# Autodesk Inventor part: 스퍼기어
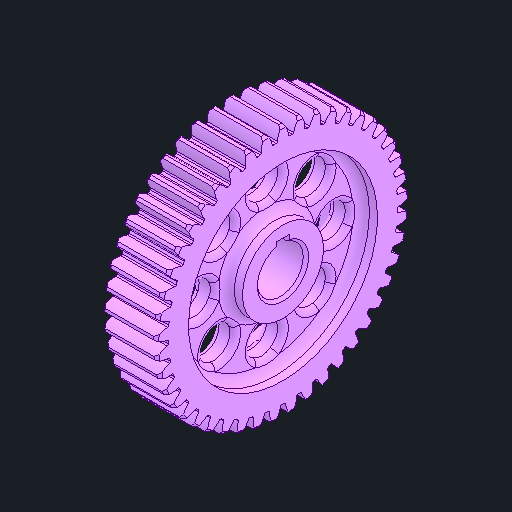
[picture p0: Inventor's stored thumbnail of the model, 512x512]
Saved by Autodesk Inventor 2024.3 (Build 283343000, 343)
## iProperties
Created: 2025-03
Part Number: 스퍼기어
Material: 강철, 합금
Document SubType Name: Modeling
Designer: user
Density: 7.73 g/cm^3
Appearance: 기본값
Author: jhkim
Sending System: Autodesk Inventor 2025
Preprocessor: ST-DEVELOPER v20
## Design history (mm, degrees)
feature "솔리드1"
node "솔리드2"
